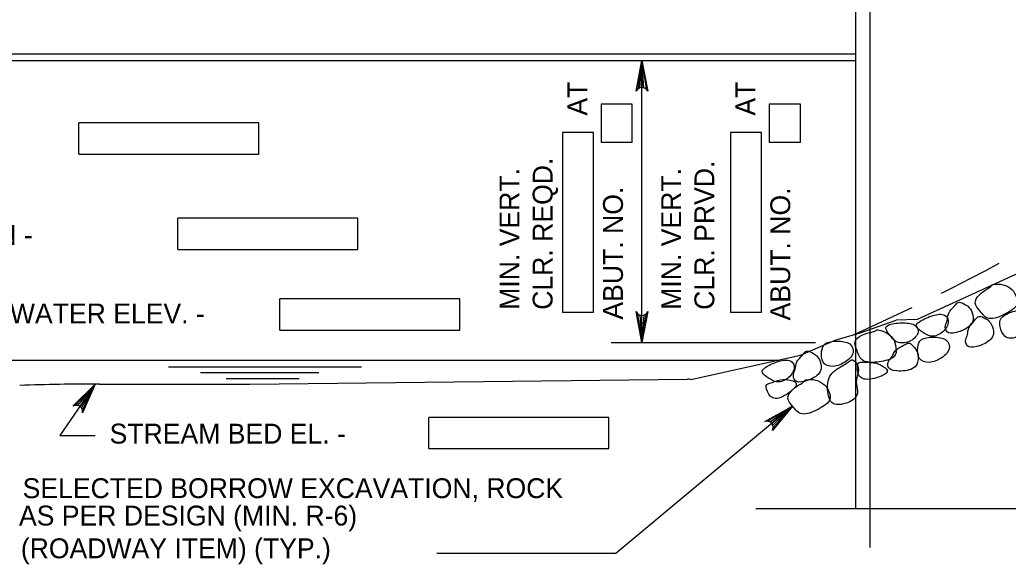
# Model space of a CAD drawing. Extents: x 638175 to 640495, y 294277 to 298435.
# Drawn here: x 638622.4 to 638771.6, y 296795 to 296877.1 of the extents above; entities that cross this region are included whole.
import ezdxf

# ---------------------------------------------------------------- set-up
doc = ezdxf.new("R2010")
doc.units = 0
for name, color, linetype in [('3', 7, 'Continuous'), ('4', 7, 'Continuous'), ('8', 7, 'Continuous')]:
    doc.layers.add(name, color=color, linetype=linetype)

msp = doc.modelspace()

# ---------------------------------------------------------------- linework, layer by layer
at = {"layer": '3'}
for p, q in [((638748.57, 296891.19), (638748.57, 296829.69)), ((638569.79, 296872.01), (638748.57, 296872.01)), ((638569.79, 296871.01), (638748.57, 296871.01)), ((638789.43, 296846.4), (638757.84, 296831.92)), ((638757.84, 296831.92), (638754.69, 296831.84)), ((638748.57, 296829.69), (638748.57, 296803.42)), ((638576.14, 296825.81), (638736.87, 296825.81)), ((638644.86, 296824.8), (638674.01, 296824.8)), ((638649.68, 296823.91), (638667.55, 296823.91)), ((638653.54, 296823.04), (638664.57, 296823.04)), ((638733.5, 296803.42), (638776.18, 296803.42))]:
    msp.add_line(p, q, dxfattribs=at)
msp.add_lwpolyline([(638634.43, 296822.18), (638657.14, 296822.18), (638723.21, 296822.9)], dxfattribs=at)
for centre, radius, start, end in [((638634.43, 296474.08), 348.1, 90, 91.9788), ((638723.2, 296811.42), 11.48, 87.4213, 90)]:
    msp.add_arc(centre, radius, start, end, dxfattribs=at)
for points in [[(638769.11, 296837.03), (638769.05, 296836.95), (638768.72, 296836.66), (638767.13, 296835.74), (638766.34, 296834.31), (638767.34, 296833.26), (638768.54, 296831.63), (638771.12, 296832.63), (638773.34, 296834.05), (638772.79, 296835.64), (638772.01, 296836.77), (638770.4, 296837.38), (638769.06, 296837.17), (638769.16, 296837.12), (638769.11, 296837.03)], [(638762.39, 296831.78), (638762.32, 296831.48), (638762.02, 296831.11), (638762.17, 296829.89), (638763.52, 296829.72), (638766.41, 296830.97), (638766.32, 296832.72), (638765.81, 296833.82), (638764.54, 296834.53), (638763.89, 296834.56), (638763.59, 296833.95), (638762.42, 296832.92), (638762.46, 296832.08), (638762.39, 296831.78)], [(638757.91, 296830.59), (638758.15, 296830.33), (638759.01, 296829.78), (638760.12, 296829.13), (638762.1, 296830.07), (638762.86, 296832), (638761.77, 296832.91), (638759.75, 296832.47), (638757.57, 296831.32), (638757.66, 296830.85), (638757.91, 296830.59)], [(638765.46, 296829.66), (638765.39, 296829.36), (638765.09, 296828.99), (638765.24, 296827.77), (638766.58, 296827.6), (638769.48, 296828.85), (638769.38, 296830.61), (638768.87, 296831.71), (638767.61, 296832.41), (638766.96, 296832.44), (638766.66, 296831.83), (638765.49, 296830.8), (638765.52, 296829.96), (638765.46, 296829.66)], [(638770.55, 296832.12), (638770.27, 296831.75), (638770.31, 296830.92), (638770.94, 296829.09), (638772.78, 296828.95), (638774.53, 296830.58), (638775.23, 296832.21), (638774.26, 296833.55), (638771.98, 296833.14), (638770.83, 296832.49), (638770.55, 296832.12)], [(638753.21, 296830.34), (638753.35, 296830.01), (638753.99, 296829.21), (638754.83, 296828.24), (638757.01, 296828.48), (638758.35, 296830.06), (638757.62, 296831.27), (638755.57, 296831.51), (638753.13, 296831.14), (638753.06, 296830.66), (638753.21, 296830.34)], [(638751.69, 296830.27), (638751.61, 296830.2), (638751.21, 296830.04), (638749.41, 296829.69), (638748.19, 296828.59), (638748.8, 296827.28), (638749.41, 296825.34), (638752.17, 296825.46), (638754.73, 296826.07), (638754.73, 296827.76), (638754.35, 296829.08), (638753.03, 296830.17), (638751.69, 296830.42), (638751.77, 296830.33), (638751.69, 296830.27)], [(638758.52, 296828.89), (638758.14, 296828.63), (638757.9, 296827.83), (638757.9, 296825.89), (638759.6, 296825.17), (638761.78, 296826.13), (638762.97, 296827.46), (638762.49, 296829.03), (638760.21, 296829.39), (638758.91, 296829.15), (638758.52, 296828.89)], [(638744.01, 296828.28), (638743.62, 296828.02), (638743.39, 296827.22), (638743.39, 296825.29), (638745.09, 296824.56), (638747.27, 296825.53), (638748.46, 296826.85), (638747.98, 296828.43), (638745.69, 296828.78), (638744.39, 296828.54), (638744.01, 296828.28)], [(638754.08, 296826.34), (638753.92, 296826.07), (638753.51, 296825.83), (638753.26, 296824.62), (638754.47, 296824.02), (638757.62, 296824.27), (638758.1, 296825.96), (638757.97, 296827.16), (638757.01, 296828.24), (638756.4, 296828.48), (638755.92, 296828), (638754.47, 296827.41), (638754.24, 296826.6), (638754.08, 296826.34)], [(638739.46, 296824.41), (638739.39, 296824.11), (638739.09, 296823.74), (638739.24, 296822.52), (638740.58, 296822.35), (638743.48, 296823.6), (638743.38, 296825.35), (638742.87, 296826.46), (638741.61, 296827.16), (638740.96, 296827.19), (638740.66, 296826.58), (638739.48, 296825.55), (638739.52, 296824.71), (638739.46, 296824.41)], [(638734.66, 296823.68), (638734.9, 296823.42), (638735.76, 296822.87), (638736.87, 296822.23), (638738.85, 296823.16), (638739.61, 296825.09), (638738.52, 296825.99), (638736.5, 296825.56), (638734.32, 296824.42), (638734.41, 296823.94), (638734.66, 296823.68)], [(638747.96, 296825.84), (638747.8, 296825.8), (638747.54, 296825.4), (638744.65, 296823.95), (638744.17, 296821.78), (638744.65, 296818.88), (638747.06, 296819.12), (638748.88, 296820.09), (638748.88, 296821.53), (638748.51, 296822.74), (638749.24, 296824.43), (638748.51, 296825.64), (638748.12, 296825.88), (638747.96, 296825.84)], [(638749.56, 296825.47), (638749.12, 296825.47), (638748.8, 296825.47), (638748.8, 296823.3), (638750.37, 296822.57), (638754.12, 296823.89), (638752.55, 296824.99), (638751.46, 296825.47), (638750.01, 296825.47), (638749.56, 296825.47)], [(638735.6, 296822.31), (638735.18, 296822.17), (638734.87, 296822.07), (638735.58, 296820.01), (638737.3, 296819.83), (638740.42, 296822.3), (638738.58, 296822.83), (638737.39, 296822.93), (638736.02, 296822.46), (638735.6, 296822.31)], [(638740.83, 296822.64), (638740.77, 296822.55), (638740.44, 296822.27), (638738.86, 296821.35), (638738.06, 296819.92), (638739.07, 296818.87), (638740.27, 296817.24), (638742.84, 296818.24), (638745.07, 296819.65), (638744.52, 296821.25), (638743.73, 296822.37), (638742.13, 296822.98), (638740.78, 296822.78), (638740.89, 296822.72), (638740.83, 296822.64)]]:
    msp.add_open_spline(points, degree=3, dxfattribs=at)
at = {"layer": '4'}
for p, q in [((638750.73, 296925.11), (638750.73, 296797.53)), ((638716.31, 296828.44), (638716.31, 296871.01)), ((638710.16, 296864.39), (638710.16, 296858.64)), ((638714.86, 296864.39), (638710.16, 296864.39)), ((638714.86, 296858.64), (638714.86, 296864.39)), ((638735.53, 296864.39), (638735.53, 296858.64)), ((638740.23, 296864.39), (638735.53, 296864.39)), ((638740.23, 296858.64), (638740.23, 296864.39)), ((638658.5, 296861.57), (638631.35, 296861.57)), ((638631.35, 296856.86), (638631.35, 296861.57)), ((638658.5, 296856.86), (638658.5, 296861.57)), ((638704.31, 296860.13), (638704.31, 296832.99)), ((638709.02, 296860.13), (638704.31, 296860.13)), ((638709.02, 296832.99), (638709.02, 296860.13)), ((638729.68, 296860.13), (638729.68, 296832.99)), ((638734.39, 296860.13), (638729.68, 296860.13)), ((638734.39, 296832.99), (638734.39, 296860.13)), ((638714.86, 296858.64), (638710.16, 296858.64)), ((638740.23, 296858.64), (638735.53, 296858.64)), ((638631.35, 296856.86), (638658.5, 296856.86)), ((638673.43, 296847.2), (638646.28, 296847.2)), ((638646.28, 296842.49), (638646.28, 296847.2)), ((638673.43, 296842.49), (638673.43, 296847.2)), ((638646.28, 296842.49), (638673.43, 296842.49)), ((638661.67, 296830.33), (638661.67, 296835.03)), ((638688.82, 296835.03), (638661.67, 296835.03)), ((638688.82, 296830.33), (638688.82, 296835.03)), ((638709.02, 296832.99), (638704.31, 296832.99)), ((638734.39, 296832.99), (638729.68, 296832.99)), ((638661.67, 296830.33), (638688.82, 296830.33)), ((638711.69, 296828.44), (638742.52, 296828.44)), ((638633.79, 296822.18), (638628.44, 296814.41)), ((638739.03, 296818.85), (638712.39, 296796.62)), ((638711.32, 296817.16), (638684.17, 296817.16)), ((638684.17, 296812.45), (638684.17, 296817.16)), ((638711.32, 296812.45), (638711.32, 296817.16)), ((638628.44, 296814.41), (638633.79, 296814.41)), ((638684.17, 296812.45), (638711.32, 296812.45)), ((638712.39, 296796.62), (638685.38, 296796.62))]:
    msp.add_line(p, q, dxfattribs=at)
for points in [[(638716.31, 296871.01), (638717.19, 296866.35), (638716.94, 296866.71), (638716.63, 296866.89), (638716.31, 296866.95), (638716, 296866.89), (638715.69, 296866.71), (638715.44, 296866.35), (638716.31, 296871.01), (638715.69, 296866.71), (638716, 296866.89), (638716.31, 296871.01), (638716.31, 296866.95), (638716.63, 296866.89), (638716.31, 296871.01), (638716.94, 296866.71)], [(638716.31, 296828.44), (638715.44, 296833.11), (638715.69, 296832.75), (638716, 296832.56), (638716.31, 296832.51), (638716.63, 296832.56), (638716.94, 296832.75), (638717.19, 296833.11), (638716.31, 296828.44), (638716.94, 296832.75), (638716.63, 296832.56), (638716.31, 296828.44), (638716.31, 296832.51), (638716, 296832.56), (638716.31, 296828.44), (638715.69, 296832.75)], [(638723.72, 296822.89), (638740.24, 296826.55), (638745.49, 296828.8), (638749.26, 296829.89), (638754.69, 296831.84)], [(638633.79, 296822.18), (638631.87, 296817.84), (638631.87, 296818.28), (638631.72, 296818.61), (638631.49, 296818.83), (638631.2, 296818.97), (638630.84, 296818.99), (638630.43, 296818.83), (638633.79, 296822.18), (638630.84, 296818.99), (638631.2, 296818.97), (638633.79, 296822.18), (638631.49, 296818.83), (638631.72, 296818.61), (638633.79, 296822.18), (638631.87, 296818.28)], [(638739.03, 296818.85), (638736.01, 296815.19), (638736.13, 296815.62), (638736.07, 296815.97), (638735.91, 296816.25), (638735.67, 296816.46), (638735.33, 296816.58), (638734.89, 296816.54), (638739.03, 296818.85), (638735.33, 296816.58), (638735.67, 296816.46), (638739.03, 296818.85), (638735.91, 296816.25), (638736.07, 296815.97), (638739.03, 296818.85), (638736.13, 296815.62)]]:
    msp.add_lwpolyline(points, dxfattribs=at)
for points in [[(638715.82, 296831.4), (638716.81, 296831.4), (638716.31, 296828.44)], [(638631.71, 296820.02), (638632.52, 296819.47), (638633.79, 296822.18)], [(638736.45, 296817.34), (638737.08, 296816.58), (638739.03, 296818.85)]]:
    msp.add_lwpolyline(points, close=True, dxfattribs=at)
at = {"layer": '8'}
for p, q in [((638768.32, 296839.37), (638770.26, 296840.42)), ((638763.12, 296836.69), (638765.87, 296838.09)), ((638765.87, 296838.09), (638768.32, 296839.37)), ((638761.52, 296835.89), (638763.12, 296836.69)), ((638756.54, 296833.46), (638757.1, 296833.73)), ((638752.6, 296831.61), (638756.54, 296833.46)), ((638748.17, 296829.58), (638752.6, 296831.61))]:
    msp.add_line(p, q, dxfattribs=at)

# ---------------------------------------------------------------- texts
at = {"layer": '4'}
for s, p in [('AT', (638708.07, 296862.68)), ('AT', (638733.44, 296862.68)), ('CLR. REQD.', (638702.83, 296833.38)), ('MIN. VERT.', (638697.83, 296833.38)), ('MIN. VERT.', (638722.24, 296833.38)), ('CLR. PRVD.', (638727.24, 296833.38)), ('ABUT. NO. ', (638713.45, 296831.9)), ('ABUT. NO. ', (638738.7, 296831.78))]:
    msp.add_text(s, height=3, rotation=90, dxfattribs=at).set_placement(p)
for s, p in [('Q        ELEVATION - ', (638587.37, 296843.17)), ('NORMAL WATER ELEV. -', (638602.64, 296831.32)), ('STREAM BED EL. -', (638635.97, 296813.2)), ('SELECTED BORROW EXCAVATION, ROCK', (638622.84, 296804.97)), ('AS PER DESIGN (MIN. R-6)', (638622.29, 296800.84)), ('(ROADWAY ITEM) (TYP.)', (638622.57, 296795.9))]:
    msp.add_text(s, height=3, dxfattribs=at).set_placement(p)

doc.saveas('drawing.dxf')
